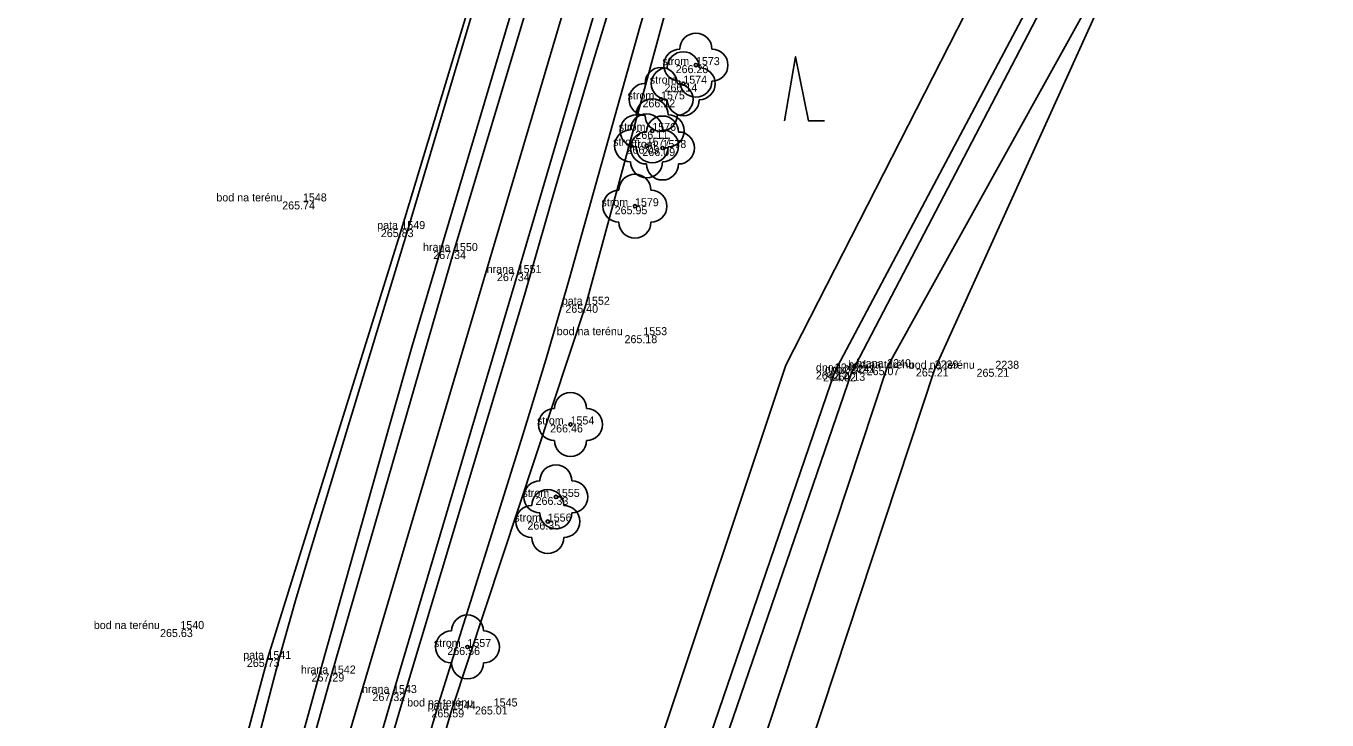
# Model space of a CAD drawing. Extents: x -567962 to -566460, y -1093720 to -1089838.
# Drawn here: x -567071.6 to -566990.3, y -1090585 to -1090541.7 of the extents above; entities that cross this region are included whole.
import ezdxf

# ---------------------------------------------------------------- set-up
doc = ezdxf.new("R2010")
doc.units = 0
for name, color, linetype in [('0_osa hráze', 7, 'Continuous'), ('bod_znacka', 7, 'Continuous'), ('cislo_bodu', 7, 'Continuous'), ('Doměření - kraj pole', 7, 'Continuous'), ('hrana_L', 7, 'Continuous'), ('kod_bodu', 7, 'Continuous'), ('norm_vrst', 7, 'Continuous'), ('ostatni', 7, 'Continuous'), ('stromy', 7, 'Continuous'), ('Vrstva 1', 7, 'Continuous'), ('vyska_bodu', 7, 'Continuous')]:
    doc.layers.add(name, color=color, linetype=linetype)

# ---------------------------------------------------------------- blocks, each defined once
blk = doc.blocks.new('3.08')
at = {"layer": 'Vrstva 1'}
blk.add_lwpolyline([(-0.07, 0), (0, 0.4), (0.08, 0), (0.18, 0)], dxfattribs=at)

msp = doc.modelspace()

# ---------------------------------------------------------------- linework, layer by layer
at = {"layer": '0_osa hráze'}
msp.add_lwpolyline([(-566992.633, -1090384.067), (-567007.197, -1090436.584), (-567067.25, -1090639.191), (-567071.646, -1090653.926)], dxfattribs=at)
at = {"layer": 'bod_znacka'}
for p, q in [((-567029.78, -1090544.11), (-567029.78, -1090544.11)), ((-567030.57, -1090545.27), (-567030.57, -1090545.27)), ((-567031.96, -1090546.25), (-567031.96, -1090546.25)), ((-567032.51, -1090548.22), (-567032.51, -1090548.22)), ((-567032.86, -1090549.15), (-567032.86, -1090549.15)), ((-567031.87, -1090549.29), (-567031.87, -1090549.29)), ((-567054.34, -1090552.63), (-567054.34, -1090552.63)), ((-567033.59, -1090552.93), (-567033.59, -1090552.93)), ((-567048.19, -1090554.36), (-567048.19, -1090554.36)), ((-567044.9, -1090555.73), (-567044.9, -1090555.73)), ((-567040.92, -1090557.11), (-567040.92, -1090557.11)), ((-567036.65, -1090559.09), (-567036.65, -1090559.09)), ((-567033.07, -1090560.99), (-567033.07, -1090560.99)), ((-567017.83, -1090562.99), (-567017.83, -1090562.99)), ((-567014.86, -1090563.07), (-567014.86, -1090563.07)), ((-567011.07, -1090563.09), (-567011.07, -1090563.09)), ((-567021.1, -1090563.26), (-567021.1, -1090563.26)), ((-567020.54, -1090563.38), (-567020.54, -1090563.38)), ((-567020.06, -1090563.34), (-567020.06, -1090563.34)), ((-567037.62, -1090566.57), (-567037.62, -1090566.57)), ((-567038.53, -1090571.1), (-567038.53, -1090571.1)), ((-567039.04, -1090572.64), (-567039.04, -1090572.64)), ((-567062, -1090579.36), (-567062, -1090579.36)), ((-567044.06, -1090580.48), (-567044.06, -1090580.48)), ((-567056.56, -1090581.23), (-567056.56, -1090581.23)), ((-567052.53, -1090582.14), (-567052.53, -1090582.14)), ((-567048.71, -1090583.36), (-567048.71, -1090583.36)), ((-567042.42, -1090584.2), (-567042.42, -1090584.2)), ((-567045.04, -1090584.38), (-567045.04, -1090584.38))]:
    msp.add_line(p, q, dxfattribs=at)
at = {"layer": 'Doměření - kraj pole'}
msp.add_lwpolyline([(-567047.906, -1090663.012), (-567047.627, -1090662.294), (-567014.86, -1090563.09), (-567002.362, -1090535.532), (-566955.49, -1090317.15), (-566941.63, -1090287.13), (-566940.57, -1090285.53), (-566924.46, -1090259.19), (-566900.35, -1090228.87), (-566877.72, -1090206.37), (-566851.19, -1090186.75), (-566766.44, -1090128.68), (-566717.21, -1090096.34), (-566711.98, -1090092.48)], dxfattribs=at)
at = {"layer": 'hrana_L'}
for p, q in [((-567048.19, -1090554.36), (-567039.62, -1090526.12)), ((-567044.9, -1090555.73), (-567036.33, -1090527.14)), ((-567040.92, -1090557.11), (-567032.34, -1090528.03)), ((-567028.42, -1090528.66), (-567036.65, -1090559.09)), ((-567056.56, -1090581.23), (-567048.19, -1090554.36)), ((-567044.9, -1090555.73), (-567052.53, -1090582.14)), ((-567040.92, -1090557.11), (-567048.71, -1090583.36)), ((-567036.65, -1090559.09), (-567045.04, -1090584.38)), ((-567056.56, -1090581.23), (-567064.73, -1090611.78)), ((-567061.28, -1090612.91), (-567052.53, -1090582.14)), ((-567048.71, -1090583.36), (-567057.43, -1090613.72)), ((-567045.04, -1090584.38), (-567053.88, -1090614.65))]:
    msp.add_line(p, q, dxfattribs=at)
for points in [[(-567053.87, -1090661.84), (-567020.06, -1090563.34), (-567005.258, -1090534.966), (-566958.763, -1090315.674), (-566944.67, -1090284.66), (-566926.49, -1090256.26), (-566902.65, -1090226.03), (-566881.28, -1090203.14), (-566853.44, -1090182.668), (-566715.257, -1090089.634)], [(-567050.54, -1090661.95), (-567017.83, -1090562.99), (-567002.61, -1090535.52), (-566957.72, -1090316.45), (-566942.31, -1090285.07), (-566925.11, -1090257.71), (-566901.37, -1090227.4), (-566879.5, -1090205.23), (-566852.16, -1090184), (-566767.57, -1090126.99), (-566713.28, -1090090.76)], [(-567054.63, -1090661.3), (-567021.1, -1090563.26), (-567005.966, -1090534.719), (-566959.79, -1090315.95), (-566954.53, -1090301.38)], [(-567056.9, -1090661.05), (-567024.166, -1090562.867), (-567008.85, -1090532.85), (-566986.05, -1090420.46), (-566964.67, -1090335.6)]]:
    msp.add_lwpolyline(points, dxfattribs=at)
at = {"layer": 'norm_vrst'}
for points in [[(-566996.014, -1090380.556), (-566996.729, -1090383.891), (-566997.836, -1090389.245), (-566998.16, -1090390.704), (-566998.565, -1090392.408), (-566999.415, -1090395.853), (-567000.577, -1090400.394), (-567003.099, -1090409.708), (-567007.472, -1090425.275), (-567010.547, -1090436.053), (-567013.879, -1090447.727), (-567016.833, -1090457.839), (-567020.353, -1090469.807), (-567022.825, -1090478.13), (-567024.79, -1090484.896), (-567028.172, -1090496.589), (-567031.048, -1090506.363), (-567037.228, -1090527.014), (-567046.993, -1090559.911), (-567047.484, -1090561.587), (-567048.887, -1090566.488), (-567053.022, -1090581.114), (-567055.12, -1090588.724)], [(-567049.953, -1090590.144), (-567048.297, -1090584.489), (-567040.503, -1090558.498), (-567039.972, -1090556.684), (-567038.82, -1090552.675), (-567038.279, -1090550.821), (-567036.614, -1090545.257), (-567032.664, -1090532.219), (-567031.35, -1090527.828), (-567027.02, -1090512.891), (-567025.39, -1090507.378), (-567024.313, -1090503.813), (-567022.688, -1090498.527), (-567019.868, -1090489.514), (-567016.268, -1090478.09)], [(-567047.076, -1090588.184), (-567045.854, -1090583.977), (-567040.678, -1090567.485), (-567040.181, -1090565.873), (-567039.168, -1090562.531), (-567038.192, -1090559.24), (-567037.675, -1090557.426), (-567034.982, -1090547.75), (-567033.279, -1090541.737), (-567031.572, -1090535.819), (-567028.863, -1090526.739), (-567027.241, -1090521.291), (-567026.223, -1090518.024), (-567022.288, -1090505.782), (-567021.269, -1090502.56), (-567020.711, -1090500.763), (-567019.81, -1090497.96), (-567018.867, -1090495.097), (-567017.637, -1090491.791), (-567016.545, -1090488.775), (-567015.461, -1090485.7), (-567014.383, -1090482.534), (-567013.312, -1090479.251)], [(-567025.817, -1090480.413), (-567029.333, -1090492.025), (-567030.341, -1090495.442), (-567032.587, -1090503.199), (-567037.894, -1090521.152), (-567039.05, -1090525.097), (-567041.711, -1090533.924), (-567047.346, -1090552.919), (-567047.876, -1090554.686), (-567053.853, -1090574.365), (-567054.803, -1090577.576), (-567055.717, -1090580.821), (-567056.18, -1090582.553), (-567059.106, -1090593.771)]]:
    msp.add_lwpolyline(points, dxfattribs=at)
at = {"layer": 'stromy'}
for centre in [(-567029.78, -1090544.11), (-567030.57, -1090545.27), (-567031.96, -1090546.25), (-567032.51, -1090548.22), (-567032.86, -1090549.15), (-567031.87, -1090549.29), (-567033.59, -1090552.93), (-567037.62, -1090566.57), (-567038.53, -1090571.1), (-567039.04, -1090572.64), (-567044.06, -1090580.48)]:
    msp.add_circle(centre, 0.1, dxfattribs=at)
for centre, start, end in [((-567029.78, -1090543.11), 0, 180), ((-567030.78, -1090544.11), 90, 270), ((-567030.57, -1090544.27), 0, 180), ((-567028.78, -1090544.11), 270, 90), ((-567031.96, -1090545.25), 0, 180), ((-567031.57, -1090545.27), 90, 270), ((-567029.57, -1090545.27), 270, 90), ((-567032.96, -1090546.25), 90, 270), ((-567030.96, -1090546.25), 270, 90), ((-567029.78, -1090545.11), 180, 0), ((-567032.51, -1090547.22), 0, 180), ((-567030.57, -1090546.27), 180, 0), ((-567033.51, -1090548.22), 90, 270), ((-567032.86, -1090548.15), 0, 180), ((-567031.96, -1090547.25), 180, 0), ((-567031.87, -1090548.29), 0, 180), ((-567031.51, -1090548.22), 270, 90), ((-567033.86, -1090549.15), 90, 270), ((-567032.87, -1090549.29), 90, 270), ((-567031.86, -1090549.15), 270, 90), ((-567030.87, -1090549.29), 270, 90), ((-567032.51, -1090549.22), 180, 0), ((-567032.86, -1090550.15), 180, 0), ((-567033.59, -1090551.93), 0, 180), ((-567031.87, -1090550.29), 180, 0), ((-567034.59, -1090552.93), 90, 270), ((-567032.59, -1090552.93), 270, 90), ((-567033.59, -1090553.93), 180, 0), ((-567037.62, -1090565.57), 0, 180), ((-567038.62, -1090566.57), 90, 270), ((-567036.62, -1090566.57), 270, 90), ((-567037.62, -1090567.57), 180, 0), ((-567038.53, -1090570.1), 0, 180), ((-567039.53, -1090571.1), 90, 270), ((-567037.53, -1090571.1), 270, 90), ((-567039.04, -1090571.64), 0, 180), ((-567040.04, -1090572.64), 90, 270), ((-567038.53, -1090572.1), 180, 0), ((-567038.04, -1090572.64), 270, 90), ((-567039.04, -1090573.64), 180, 0), ((-567044.06, -1090579.48), 0, 180), ((-567045.06, -1090580.48), 90, 270), ((-567043.06, -1090580.48), 270, 90), ((-567044.06, -1090581.48), 180, 0)]:
    msp.add_arc(centre, 1, start, end, dxfattribs=at)

# ---------------------------------------------------------------- block references
at = {"layer": 'ostatni', "xscale": 10, "yscale": 10}
msp.add_blockref('3.08', (-567023.55, -1090547.591), dxfattribs=at)

# ---------------------------------------------------------------- texts
at = {"layer": 'cislo_bodu'}
for s, p in [('1573', (-567029.78, -1090544.11)), ('1574', (-567030.57, -1090545.27)), ('1575', (-567031.96, -1090546.25)), ('1576', (-567032.51, -1090548.22)), ('1577', (-567032.86, -1090549.15)), ('1578', (-567031.87, -1090549.29)), ('1548', (-567054.34, -1090552.63)), ('1579', (-567033.59, -1090552.93)), ('1549', (-567048.19, -1090554.36)), ('1550', (-567044.9, -1090555.73)), ('1551', (-567040.92, -1090557.11)), ('1552', (-567036.65, -1090559.09)), ('1553', (-567033.07, -1090560.99)), ('2243', (-567021.1, -1090563.26)), ('2242', (-567020.54, -1090563.38)), ('2241', (-567020.06, -1090563.34)), ('2240', (-567017.83, -1090562.99)), ('2239', (-567014.86, -1090563.07)), ('2238', (-567011.07, -1090563.09)), ('1554', (-567037.62, -1090566.57)), ('1555', (-567038.53, -1090571.1)), ('1556', (-567039.04, -1090572.64)), ('1540', (-567062, -1090579.36)), ('1557', (-567044.06, -1090580.48)), ('1541', (-567056.56, -1090581.23)), ('1542', (-567052.53, -1090582.14)), ('1543', (-567048.71, -1090583.36)), ('1544', (-567045.04, -1090584.38)), ('1545', (-567042.42, -1090584.2))]:
    msp.add_text(s, height=0.5, dxfattribs=at).set_placement(p)
at = {"layer": 'kod_bodu'}
for s, p in [('strom', (-567031.874, -1090544.11)), ('strom', (-567032.664, -1090545.27)), ('strom', (-567034.054, -1090546.25)), ('strom', (-567034.604, -1090548.22)), ('strom', (-567034.954, -1090549.15)), ('strom', (-567033.964, -1090549.29)), ('bod na terénu', (-567059.749, -1090552.63)), ('strom', (-567035.684, -1090552.93)), ('pata', (-567049.702, -1090554.36)), ('hrana', (-567046.837, -1090555.73)), ('hrana', (-567042.857, -1090557.11)), ('pata', (-567038.162, -1090559.09)), ('bod na terénu', (-567038.479, -1090560.99)), ('dno', (-567022.281, -1090563.26)), ('dno', (-567021.721, -1090563.38)), ('dno', (-567021.241, -1090563.34)), ('bod na terénu', (-567020.269, -1090563.07)), ('hrana', (-567019.767, -1090562.99)), ('bod na terénu', (-567016.479, -1090563.09)), ('strom', (-567039.714, -1090566.57)), ('strom', (-567040.624, -1090571.1)), ('strom', (-567041.134, -1090572.64)), ('bod na terénu', (-567067.409, -1090579.36)), ('strom', (-567046.154, -1090580.48)), ('pata', (-567058.072, -1090581.23)), ('hrana', (-567054.467, -1090582.14)), ('hrana', (-567050.647, -1090583.36)), ('bod na terénu', (-567047.829, -1090584.2)), ('pata', (-567046.552, -1090584.38))]:
    msp.add_text(s, height=0.5, dxfattribs=at).set_placement(p)
at = {"layer": 'vyska_bodu'}
for s, p in [('266.20', (-567031.048, -1090544.61)), ('266.14', (-567031.743, -1090545.77)), ('266.12', (-567033.121, -1090546.75)), ('266.11', (-567033.563, -1090548.72)), ('266.09', (-567034.116, -1090549.65)), ('266.09', (-567033.126, -1090549.79)), ('265.74', (-567055.635, -1090553.13)), ('265.95', (-567034.86, -1090553.43)), ('265.83', (-567049.471, -1090554.86)), ('267.34', (-567046.195, -1090556.23)), ('267.34', (-567042.215, -1090557.61)), ('265.40', (-567037.941, -1090559.59)), ('265.18', (-567034.243, -1090561.49)), ('265.07', (-567019.111, -1090563.49)), ('265.21', (-567016.033, -1090563.57)), ('265.21', (-567012.243, -1090563.59)), ('264.12', (-567022.285, -1090563.76)), ('264.02', (-567021.831, -1090563.88)), ('264.13', (-567021.245, -1090563.84)), ('266.46', (-567038.89, -1090567.07)), ('266.33', (-567039.8, -1090571.6)), ('266.35', (-567040.31, -1090573.14)), ('265.63', (-567063.27, -1090579.86)), ('266.56', (-567045.318, -1090580.98)), ('265.73', (-567057.843, -1090581.73)), ('267.29', (-567053.802, -1090582.64)), ('267.32', (-567049.993, -1090583.86)), ('265.59', (-567046.31, -1090584.88)), ('265.01', (-567043.591, -1090584.7))]:
    msp.add_text(s, height=0.5, dxfattribs=at).set_placement(p)

doc.saveas('drawing.dxf')
